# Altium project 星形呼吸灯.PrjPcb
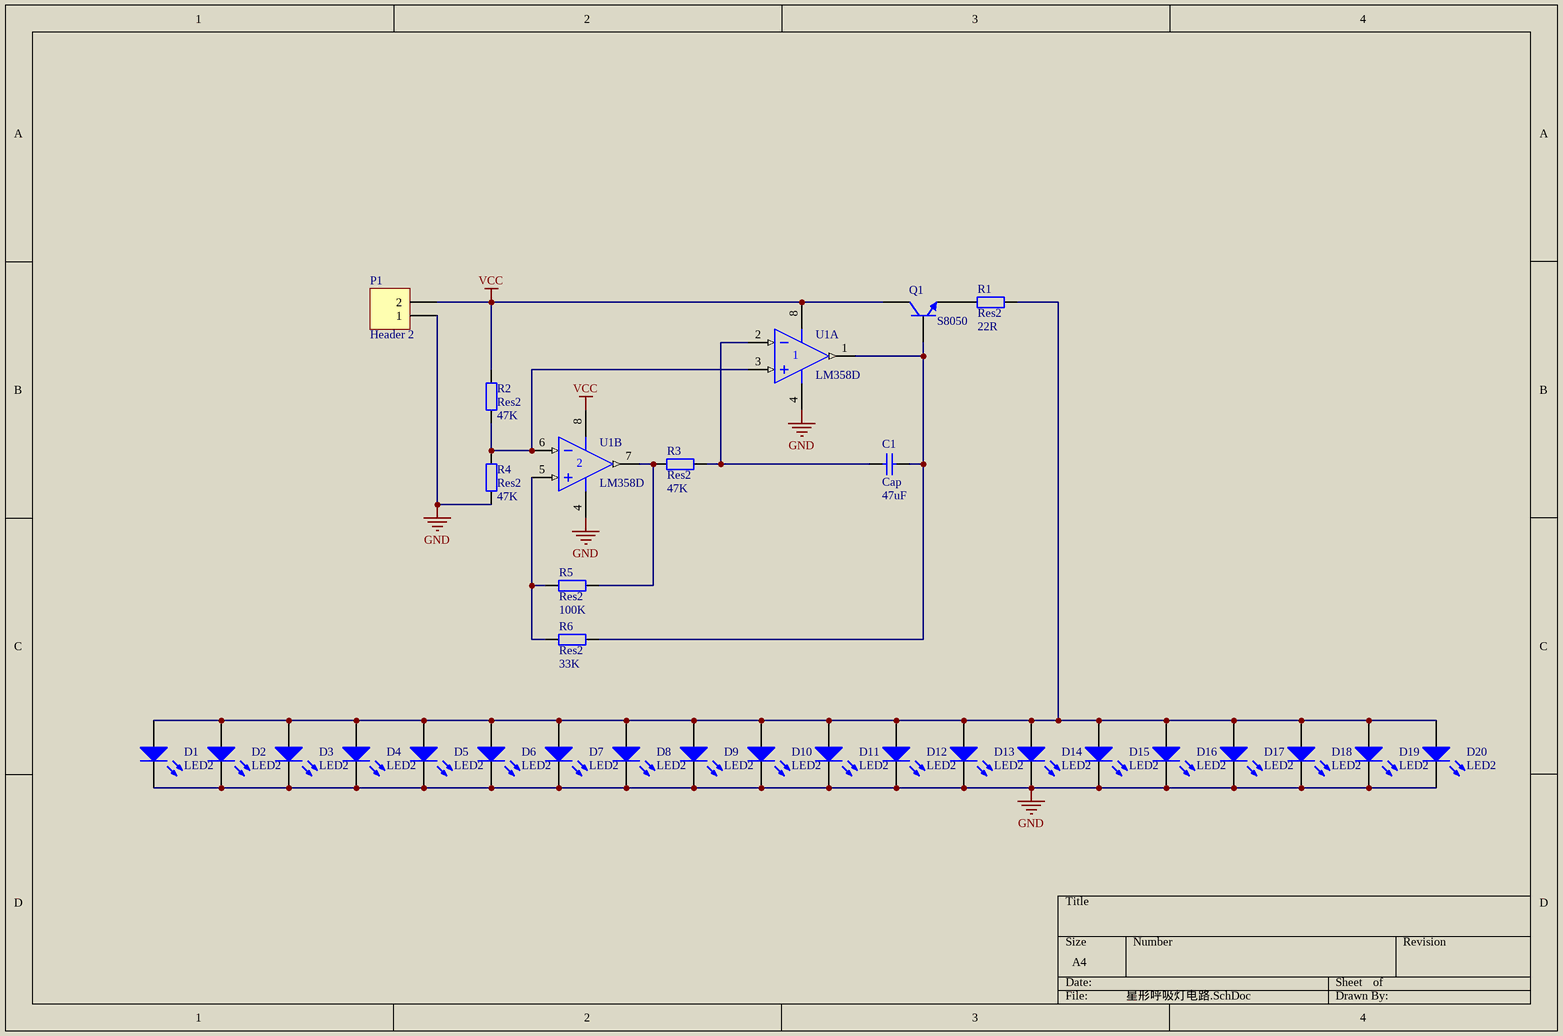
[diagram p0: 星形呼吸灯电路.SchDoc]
1 sheet, 30 parts. Net scope: global (net labels, ports and power ports of the same name join across sheets).
Board file: 星形呼吸灯PCB.PcbDoc

## Sheet 星形呼吸灯电路.SchDoc
size A4

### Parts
C1  Cap  value 47uF  [C0805]
D1  LED2  [LED0805-R-RD]
D2  LED2  [LED0805-R-RD]
D3  LED2  [LED0805-R-RD]
D4  LED2  [LED0805-R-RD]
D5  LED2  [LED0805-R-RD]
D6  LED2  [LED0805-R-RD]
D7  LED2  [LED0805-R-RD]
D8  LED2  [LED0805-R-RD]
D9  LED2  [LED0805-R-RD]
D10  LED2  [LED0805-R-RD]
D11  LED2  [LED0805-R-RD]
D12  LED2  [LED0805-R-RD]
D13  LED2  [LED0805-R-RD]
D14  LED2  [LED0805-R-RD]
D15  LED2  [LED0805-R-RD]
D16  LED2  [LED0805-R-RD]
D17  LED2  [LED0805-R-RD]
D18  LED2  [LED0805-R-RD]
D19  LED2  [LED0805-R-RD]
D20  LED2  [LED0805-R-RD]
P1  Header 2  [HDR1X2]
Q1  S8050  [S8050-J3Y]
R1  Res2  value 22R  [R0805]
R2  Res2  value 47K  [R0805]
R3  Res2  value 47K  [R0805]
R4  Res2  value 47K  [R0805]
R5  Res2  value 100K  [R0805]
R6  Res2  value 33K  [R0805]
U1  LM358D  [751-02]  (parts A,B of 2)

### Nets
GND: D1.2(K) D2.2(K) D3.2(K) D4.2(K) D5.2(K) D6.2(K) D7.2(K) D8.2(K) D9.2(K) D10.2(K) D11.2(K) D12.2(K) D13.2(K) D14.2(K) D15.2(K) D16.2(K) D17.2(K) D18.2(K) D19.2(K) D20.2(K) P1.1 R4.1 U1.4(V-)
VCC: P1.2 Q1.1(C) R2.2 U1.8(V+)
NetC1_1: C1.1 R3.1 U1.2(IN-)
NetC1_2: C1.2 Q1.2(B) R6.1 U1.1(OUT)
NetD1_1: D1.1(A) D2.1(A) D3.1(A) D4.1(A) D5.1(A) D6.1(A) D7.1(A) D8.1(A) D9.1(A) D10.1(A) D11.1(A) D12.1(A) D13.1(A) D14.1(A) D15.1(A) D16.1(A) D17.1(A) D18.1(A) D19.1(A) D20.1(A) R1.1
NetQ1_3: Q1.3(E) R1.2
NetR2_1: R2.1 R4.2 U1.3(IN+) U1.6(IN-)
NetR3_2: R3.2 R5.1 U1.7(OUT)
NetR5_2: R5.2 R6.2 U1.5(IN+)

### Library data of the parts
C1 = Cap: Capacitor
D1-D20 = LED2: Typical RED, GREEN, YELLOW, AMBER GaAs LED
P1 = Header 2: Header, 2-Pin
Q1 = NPN: NPN Bipolar Transistor
R1-R6 = Res2: Resistor
U1 = LM358D: Dual Low-Power Operational Amplifier; Code - JEDEC: MS-012-AA; Code - IPC: SO8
